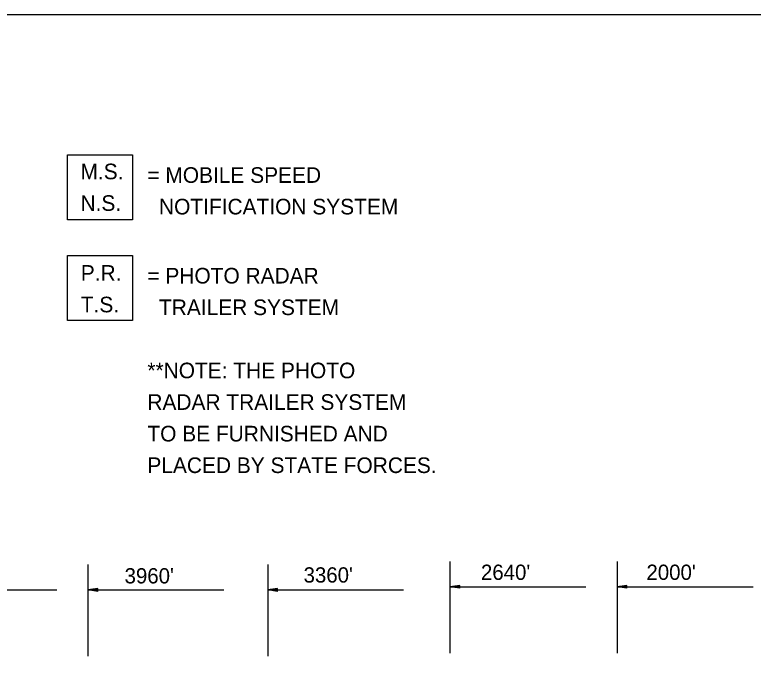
# Model space of a CAD drawing. Extents: x -100 to 745, y -1581 to -107.
# Drawn here: x 610.84 to 639.18, y -511.57 to -486.79 of the extents above; entities that cross this region are included whole.
import ezdxf

# ---------------------------------------------------------------- set-up
doc = ezdxf.new("R2010")
doc.units = 0
doc.layers.add('Default', color=7, linetype='Continuous')
doc.layers.add('R_Proposed Road', color=7, linetype='Continuous')

msp = doc.modelspace()

# ---------------------------------------------------------------- linework, layer by layer
at = {"layer": 'Default'}
for p, q in [((613.642, -507.896), (613.642, -511.417)), ((620.542, -507.896), (620.542, -511.417)), ((627.539, -507.776), (627.539, -511.297)), ((633.955, -507.776), (633.955, -511.297)), ((627.914, -508.699), (627.539, -508.755)), ((627.539, -508.755), (632.758, -508.755)), ((627.914, -508.811), (627.539, -508.755)), ((627.914, -508.708), (627.601, -508.755)), ((627.914, -508.802), (627.601, -508.755)), ((627.914, -508.718), (627.666, -508.755)), ((627.914, -508.792), (627.666, -508.755)), ((627.914, -508.727), (627.728, -508.755)), ((627.914, -508.783), (627.728, -508.755)), ((627.914, -508.736), (627.792, -508.755)), ((627.914, -508.773), (627.792, -508.755)), ((627.914, -508.746), (627.854, -508.755)), ((627.914, -508.764), (627.854, -508.755)), ((627.914, -508.811), (627.914, -508.699)), ((634.33, -508.699), (633.955, -508.755)), ((633.955, -508.755), (639.174, -508.755)), ((634.33, -508.811), (633.955, -508.755)), ((634.33, -508.708), (634.017, -508.755)), ((634.33, -508.802), (634.017, -508.755)), ((634.33, -508.718), (634.082, -508.755)), ((634.33, -508.792), (634.082, -508.755)), ((634.33, -508.727), (634.144, -508.755)), ((634.33, -508.783), (634.144, -508.755)), ((634.33, -508.736), (634.208, -508.755)), ((634.33, -508.773), (634.208, -508.755)), ((634.33, -508.746), (634.271, -508.755)), ((634.33, -508.764), (634.271, -508.755)), ((634.33, -508.811), (634.33, -508.699)), ((607.226, -508.875), (612.445, -508.875)), ((614.017, -508.818), (613.642, -508.875)), ((613.642, -508.875), (618.861, -508.875)), ((614.017, -508.931), (613.642, -508.875)), ((614.017, -508.828), (613.704, -508.875)), ((614.017, -508.922), (613.704, -508.875)), ((614.017, -508.837), (613.769, -508.875)), ((614.017, -508.912), (613.769, -508.875)), ((614.017, -508.847), (613.831, -508.875)), ((614.017, -508.903), (613.831, -508.875)), ((614.017, -508.856), (613.895, -508.875)), ((614.017, -508.893), (613.895, -508.875)), ((614.017, -508.866), (613.957, -508.875)), ((614.017, -508.884), (613.957, -508.875)), ((614.017, -508.931), (614.017, -508.818)), ((620.917, -508.818), (620.542, -508.875)), ((620.542, -508.875), (625.761, -508.875)), ((620.917, -508.931), (620.542, -508.875)), ((620.917, -508.828), (620.605, -508.875)), ((620.917, -508.922), (620.605, -508.875)), ((620.917, -508.837), (620.669, -508.875)), ((620.917, -508.912), (620.669, -508.875)), ((620.917, -508.847), (620.732, -508.875)), ((620.917, -508.903), (620.732, -508.875)), ((620.917, -508.856), (620.795, -508.875)), ((620.917, -508.893), (620.795, -508.875)), ((620.917, -508.866), (620.858, -508.875)), ((620.917, -508.884), (620.858, -508.875)), ((620.917, -508.931), (620.917, -508.818))]:
    msp.add_line(p, q, dxfattribs=at)
for points in [[(612.86, -494.665), (612.86, -492.165), (615.36, -492.165), (615.36, -494.665)], [(612.86, -498.53), (612.86, -496.03), (615.36, -496.03), (615.36, -498.53)]]:
    msp.add_lwpolyline(points, close=True, dxfattribs=at)
at = {"layer": 'R_Proposed Road'}
msp.add_lwpolyline([(574.769, -486.786), (574.769, -596.786), (744.769, -596.786), (744.769, -486.786)], close=True, dxfattribs=at)

# ---------------------------------------------------------------- texts
at = {"layer": 'Default'}
for s, height, p in [('M.S.', 0.6, (613.358, -493.104)), ('= MOBILE SPEED', 0.6, (615.925, -493.241)), ('N.S.', 0.6, (613.358, -494.317)), ('  NOTIFICATION SYSTEM', 0.6, (615.925, -494.454)), ('P.R.', 0.6, (613.369, -497)), ('= PHOTO RADAR', 0.6, (615.925, -497.106)), ('T.S.', 0.6, (613.369, -498.213)), ('  TRAILER SYSTEM', 0.6, (615.925, -498.319)), ('**NOTE: THE PHOTO', 0.6, (615.925, -500.745)), ('RADAR TRAILER SYSTEM', 0.6, (615.925, -501.958)), ('TO BE FURNISHED AND', 0.6, (615.925, -503.171)), ('PLACED BY STATE FORCES.', 0.6, (615.925, -504.384)), ("2640'", 0.5862, (628.728, -508.487)), ("2000'", 0.5862, (635.08, -508.487)), ("3960'", 0.5862, (615.05, -508.623)), ("3360'", 0.5862, (621.92, -508.59))]:
    msp.add_text(s, height=height, dxfattribs=at).set_placement(p)

doc.saveas('drawing.dxf')
